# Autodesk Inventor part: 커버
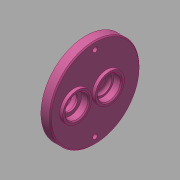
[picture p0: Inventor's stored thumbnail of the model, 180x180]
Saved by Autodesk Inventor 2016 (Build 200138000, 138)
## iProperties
Created: 2016-02
Part Number: 커버
Material: 알루미늄 6061
Document SubType Name: Modeling
Designer: mduedu
Density: 2.71 g/cm^3
Appearance: 분홍색
Author: mduedu
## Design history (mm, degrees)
sketch "스케치1"
  geometry: C1 r 43 at (0, 0); 1 further point
  constraints: 1 centre point, 1 coincident
  dimensions: "d0" = 86 diameter of C1
extrude "돌출1" new body sketch "스케치1" distance "d1" = 9; taper "d2" = 0 deg
sketch "스케치2"
  geometry: C1 r 14 at (0, 11); 1 further point
  constraints: 1 centre point, 1 vertical alignment
  dimensions: "d3" = 28 diameter of C1; "d6" = 11 distance of C1.centre point (0, 0)
extrude "돌출2" join sketch "스케치2" distance "d7" = 3; taper "d8" = 0 deg
sketch "스케치3"
  geometry: C1 r 14 at (0, -20); 1 further point
  constraints: 1 centre point, 1 vertical alignment
  dimensions: "d9" = 28 diameter of C1; "d10" = 20 distance of C1.centre point (0, 0)
extrude "돌출3" join sketch "스케치3" distance "d11" = 3; taper "d12" = 0 deg
hole "구멍1" diameter "d15" = 22; stored, may be unused: countersink angle "d19" = 90 deg, drill point angle "d21" = 0 deg; dims "d13" = 10, "d14" = 10, "d16" = 6, "d17" = 4, "d18" = 2, "d20" = 7
hole "구멍2" diameter "d24" = 18; stored, may be unused: countersink angle "d28" = 90 deg, drill point angle "d30" = 0 deg; dims "d25" = 6, "d26" = 4, "d27" = 2, "d29" = 3, "d95" = 10, "d96" = 10
fillet "모깎기7" dims "d97" = 3
hole "구멍3" diameter "d33" = 22; stored, may be unused: countersink angle "d37" = 90 deg, drill point angle "d39" = 0 deg; dims "d34" = 6, "d35" = 4, "d36" = 2, "d38" = 7, "d73" = 10, "d74" = 10
sketch "스케치4"
  geometry: C1 r 14 at (0, -20) reference; C2 r 18 at (0, -20); 1 further point
  constraints: 1 centre point, 1 coincident
  dimensions: "d40" = 36 diameter of C2
extrude "돌출4" join sketch "스케치4" distance "d41" = 4; taper "d42" = 0 deg
hole "구멍4" diameter "d45" = 22; stored, may be unused: countersink angle "d49" = 90 deg, drill point angle "d51" = 0 deg; dims "d46" = 6, "d47" = 4, "d48" = 2, "d50" = 7.3, "d98" = 10, "d99" = 10
hole "구멍5" diameter "d54" = 15; stored, may be unused: countersink angle "d58" = 90 deg, drill point angle "d60" = 0 deg; dims "d52" = 10, "d53" = 10, "d55" = 6, "d56" = 4, "d57" = 2, "d59" = 7
chamfer "모따기1" distance "d63" = 1; stored, may be unused: second distance "d64" = 2, angle "d65" = 45 deg
chamfer "모따기3" distance "d100" = 0.7; stored, may be unused: second distance "d101" = 2, angle "d102" = 30 deg
sketch "스케치5" dims "d67" = 72
  geometry: 4 further points
  constraints: 2 horizontal alignment, 1 coincident, 5 other
  dimensions: "d71" = 360 deg dimension on point (0, 0) point (-36, 0) (derived)
sketch "스케치6"
  geometry: 2 further points
hole "구멍6" sketch "스케치6" at (-36, 0), (36, 0) diameter "d76" = 4.5; stored, may be unused: countersink angle "d80" = 90 deg, drill point angle "d82" = 0 deg; dims "d77" = 6, "d78" = 8, "d79" = 4.6, "d81" = 8
chamfer "모따기2" distance "d90" = 1; stored, may be unused: second distance "d91" = 2, angle "d92" = 45 deg
node "솔리드1"
